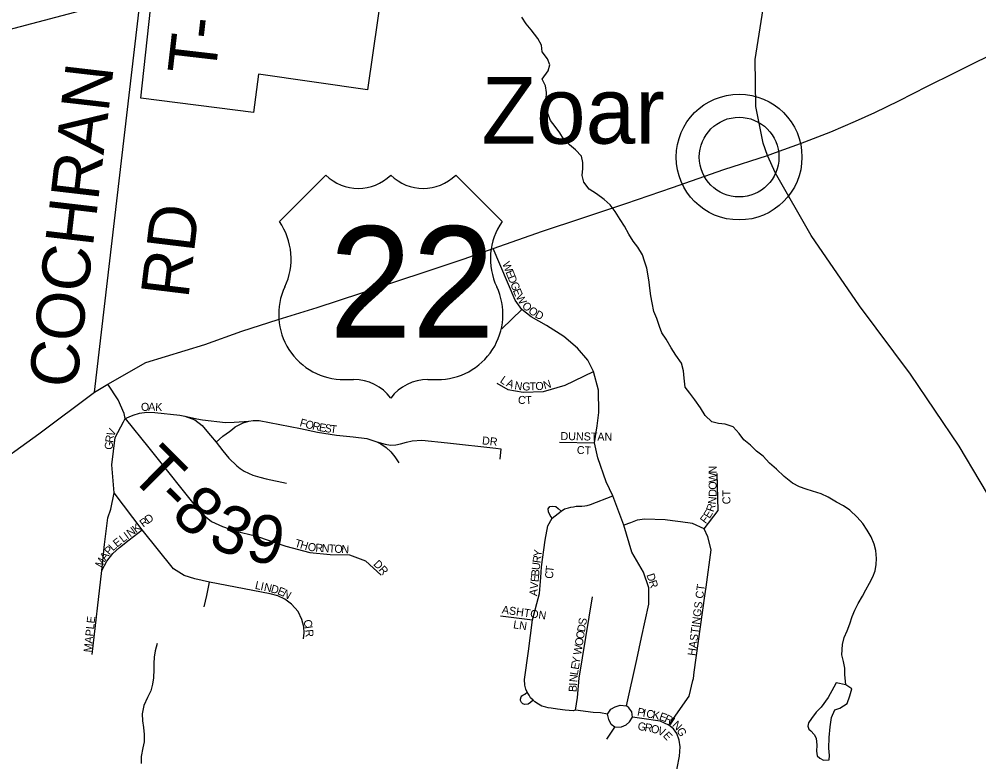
# Model space of a CAD drawing. Extents: x 0 to 34, y -4 to 22.
# Drawn here: x 5.794 to 6.594, y 16.264 to 16.882 of the extents above; entities that cross this region are included whole.
import ezdxf

# ---------------------------------------------------------------- set-up
doc = ezdxf.new("R2010")
doc.units = 0
for name, color, linetype in [('GM_X_Corporation', 7, 'Continuous'), ('GM_X_County_Road', 7, 'Continuous'), ('GM_X_Minor_Lake', 7, 'Continuous'), ('GM_X_Minor_River', 7, 'Continuous'), ('GM_X_Township_Road', 7, 'Continuous'), ('GM_X_Township_Road_Text', 7, 'Continuous'), ('GM_X_Township_Subdivision', 7, 'Continuous'), ('GM_X_Township_Subdivision_Text', 7, 'Continuous'), ('GM_X_Unincorporated', 7, 'Continuous'), ('GM_X_Unincorporated_Text', 7, 'Continuous'), ('GM_X_US_Route', 7, 'Continuous'), ('GM_X_US_Shield', 7, 'Continuous')]:
    doc.layers.add(name, color=color, linetype=linetype)

msp = doc.modelspace()

# ---------------------------------------------------------------- linework, layer by layer
at = {"layer": 'GM_X_Corporation'}
msp.add_lwpolyline([(6.11264, 17.35661), (6.13056, 17.34146), (6.1502, 17.32861), (6.15372, 17.31617), (6.14829, 17.26619), (6.13072, 17.14425), (6.11033, 17.00278), (6.08447, 16.8233), (5.99367, 16.83639), (5.98966, 16.80464), (5.89561, 16.81652), (5.90507, 16.90361), (5.90894, 16.90463), (5.90928, 16.91075), (5.90918, 16.91835), (5.91273, 16.93477), (5.92073, 16.94425), (5.92992, 16.96003), (5.93228, 16.96767), (5.89327, 16.9805), (5.87524, 16.89709), (5.63389, 16.83333)], dxfattribs=at)
at = {"layer": 'GM_X_County_Road'}
msp.add_lwpolyline([(6.61254, 16.4676), (6.57752, 16.52648), (6.53717, 16.58653), (6.49462, 16.64341), (6.45426, 16.70212), (6.42446, 16.75396), (6.41787, 16.7687), (6.41423, 16.779), (6.40811, 16.80957), (6.4076, 16.84871), (6.41599, 16.90164), (6.41166, 16.91348), (6.37222, 16.96469), (6.33546, 17.00676), (6.31619, 17.02672), (6.30338, 17.04608), (6.29642, 17.06037), (6.28477, 17.08116), (6.25889, 17.11808), (6.2527, 17.12703), (6.24616, 17.12926), (6.23635, 17.13047), (6.17768, 17.13907), (6.12342, 17.14557)], dxfattribs=at)
at = {"layer": 'GM_X_Minor_Lake'}
for points in [[(6.47509, 16.32945), (6.47312, 16.32575), (6.46835, 16.31732), (6.46279, 16.30917), (6.4584, 16.305), (6.45452, 16.29976), (6.45201, 16.29608)], [(6.48307, 16.32764), (6.47509, 16.32945)], [(6.45201, 16.29608), (6.45141, 16.29342), (6.45241, 16.29072), (6.45398, 16.28934), (6.45685, 16.28633), (6.45838, 16.28336), (6.45903, 16.27746), (6.45863, 16.27239), (6.45934, 16.26863), (6.46143, 16.26671), (6.4646, 16.26502), (6.46942, 16.26517), (6.46952, 16.26891), (6.46914, 16.27507), (6.46937, 16.28388), (6.47013, 16.29268), (6.47114, 16.30068), (6.47398, 16.30702), (6.47829, 16.30825), (6.48428, 16.31211), (6.48659, 16.31874), (6.48807, 16.32431), (6.48307, 16.32764)]]:
    msp.add_lwpolyline(points, dxfattribs=at)
at = {"layer": 'GM_X_Minor_River'}
for points in [[(6.22968, 16.86058), (6.22657, 16.86624), (6.22107, 16.87328), (6.21687, 16.87843), (6.21322, 16.88383)], [(6.48307, 16.32764), (6.4825, 16.33636), (6.48232, 16.34171), (6.48135, 16.34734), (6.47983, 16.35271), (6.48051, 16.36126), (6.48194, 16.36711), (6.48445, 16.37269), (6.48641, 16.37854), (6.48839, 16.38466), (6.49062, 16.38997), (6.49339, 16.39554), (6.49697, 16.40163), (6.5, 16.40693), (6.50303, 16.41249), (6.5058, 16.4178), (6.50776, 16.42285), (6.50838, 16.42791), (6.50873, 16.43299), (6.50831, 16.43968), (6.50679, 16.44505), (6.50422, 16.45097), (6.5011, 16.45663), (6.49745, 16.46204), (6.49272, 16.46746), (6.48667, 16.47317), (6.48138, 16.477), (6.47555, 16.48003), (6.46839, 16.48415), (6.46255, 16.48692), (6.45537, 16.48917), (6.45005, 16.49086), (6.44446, 16.49282), (6.43863, 16.49585), (6.43177, 16.50131), (6.42545, 16.50729), (6.41965, 16.51246), (6.41439, 16.51815), (6.40885, 16.52252), (6.40385, 16.52741), (6.3983, 16.53178), (6.39438, 16.53718), (6.38939, 16.54261), (6.38274, 16.54485), (6.37713, 16.54548), (6.37154, 16.5469), (6.36601, 16.55207), (6.36211, 16.55855), (6.35741, 16.5653), (6.35322, 16.57072), (6.34929, 16.57586), (6.34835, 16.58336), (6.34791, 16.58925), (6.34615, 16.59569), (6.34144, 16.60245), (6.33753, 16.60839), (6.33337, 16.61567), (6.32999, 16.62108), (6.32793, 16.62619), (6.32564, 16.63291), (6.32333, 16.63882), (6.32185, 16.64606), (6.3206, 16.6517), (6.31991, 16.65812), (6.31919, 16.66322), (6.31848, 16.66857), (6.31751, 16.67474), (6.31547, 16.68065), (6.31369, 16.68602), (6.30978, 16.69224), (6.30612, 16.69737), (6.30248, 16.70331), (6.29884, 16.70978), (6.29519, 16.71546), (6.29102, 16.72194), (6.28684, 16.72762), (6.28183, 16.73197), (6.27549, 16.73689), (6.2694, 16.74072), (6.26495, 16.74641), (6.26344, 16.75205), (6.26407, 16.75792), (6.26416, 16.763), (6.26291, 16.7681), (6.25791, 16.77352), (6.2529, 16.77761), (6.2479, 16.7825), (6.24477, 16.78763), (6.24112, 16.79277), (6.23719, 16.79791), (6.23488, 16.80382), (6.23364, 16.80973), (6.23347, 16.81561), (6.23384, 16.82122), (6.23286, 16.82685), (6.23028, 16.83224), (6.23521, 16.83911), (6.23663, 16.84416), (6.23457, 16.84928), (6.23012, 16.85496), (6.22968, 16.86058)], [(5.90942, 16.36229), (5.90771, 16.35617), (5.90682, 16.35084), (5.90646, 16.3455), (5.90665, 16.34042), (5.90627, 16.33374), (5.90537, 16.3284), (5.90394, 16.32281), (5.90117, 16.31724), (5.89812, 16.31061), (5.89693, 16.30368), (5.8971, 16.29779), (5.89808, 16.29216), (5.89852, 16.28628), (5.89842, 16.2804), (5.89753, 16.27533), (5.89607, 16.26814), (5.89597, 16.26226)]]:
    msp.add_lwpolyline(points, dxfattribs=at)
at = {"layer": 'GM_X_Township_Road'}
for points in [[(5.8572, 16.57167), (5.89878, 16.92871), (5.90307, 16.93929), (5.913, 16.95079), (5.91989, 16.97341)], [(5.93252, 16.55157), (5.94071, 16.54855), (5.94696, 16.54391), (5.95199, 16.53753), (5.95372, 16.53542), (5.95839, 16.52992), (5.96409, 16.52269), (5.96896, 16.51672), (5.97572, 16.51012), (5.97839, 16.50792), (5.98185, 16.50572), (5.98908, 16.5025), (5.99494, 16.50065), (6.0002, 16.49939), (6.01718, 16.49586)], [(5.95839, 16.52992), (5.9641, 16.53485), (5.96956, 16.53876), (5.97198, 16.54075), (5.97446, 16.54259), (5.97667, 16.54373), (5.98108, 16.54601), (5.98567, 16.54752)], [(6.09244, 16.53014), (6.0957, 16.52853), (6.10018, 16.52558), (6.10419, 16.52177), (6.10733, 16.5178), (6.1102, 16.51344), (6.11075, 16.51258)], [(5.94863, 16.39268), (5.95073, 16.40229), (5.95291, 16.41342)]]:
    msp.add_lwpolyline(points, dxfattribs=at)
at = {"layer": 'GM_X_Township_Subdivision'}
for points in [[(6.28405, 16.28258), (6.29061, 16.29252), (6.29634, 16.29266), (6.3002, 16.29439), (6.30287, 16.29692), (6.30553, 16.30079), (6.30487, 16.30519), (6.30242, 16.30869), (6.30034, 16.31025), (6.30899, 16.34895), (6.31283, 16.36709), (6.31902, 16.39484), (6.31902, 16.4085), (6.31454, 16.42152), (6.30487, 16.43825), (6.29818, 16.46067), (6.28895, 16.48528), (6.28349, 16.49688), (6.27658, 16.51673), (6.27371, 16.5293), (6.27612, 16.54363), (6.27735, 16.55473), (6.27711, 16.57324), (6.27291, 16.58891), (6.26823, 16.59816), (6.25959, 16.60828), (6.24824, 16.61789), (6.23369, 16.62702), (6.22086, 16.63418), (6.21322, 16.64035), (6.20754, 16.64824), (6.18941, 16.69127)], [(6.19649, 16.62419), (6.21322, 16.64035)], [(6.19249, 16.57904), (6.20162, 16.57373), (6.21445, 16.57151), (6.23122, 16.57201), (6.24923, 16.57743), (6.27291, 16.58891)], [(5.88123, 16.54693), (5.88264, 16.54958), (5.88187, 16.55367), (5.87692, 16.5651), (5.86827, 16.57813)], [(5.88264, 16.54958), (5.88929, 16.55254), (5.89463, 16.55402), (5.90074, 16.55486), (5.90741, 16.55465), (5.9282, 16.55254), (5.93252, 16.55157), (5.9388, 16.55023), (5.94247, 16.54947), (5.94724, 16.54847), (5.96629, 16.54631), (5.97351, 16.54664), (5.98187, 16.5472), (5.98567, 16.54752), (5.98932, 16.54791), (5.99424, 16.54798), (6.02887, 16.54136), (6.04285, 16.53821), (6.05878, 16.53583), (6.07262, 16.53426), (6.08419, 16.53303), (6.09244, 16.53014), (6.09924, 16.52814), (6.10364, 16.52748), (6.10821, 16.52777), (6.11224, 16.52847), (6.11697, 16.52987), (6.12188, 16.5311), (6.12977, 16.53163), (6.15115, 16.52935), (6.19164, 16.52496), (6.19585, 16.52444), (6.19494, 16.51587)], [(5.85522, 16.35297), (5.86321, 16.42305), (5.8655, 16.44475), (5.86816, 16.46684), (5.87083, 16.47408), (5.8735, 16.48779), (5.87159, 16.51102), (5.87426, 16.53387), (5.88123, 16.54693)], [(5.88264, 16.54958), (5.90244, 16.52511), (5.94547, 16.47141), (5.95461, 16.4638), (5.96375, 16.45961), (5.9748, 16.4558), (5.99117, 16.45199), (6.01669, 16.44323), (6.03649, 16.4379), (6.05362, 16.43638), (6.06962, 16.436), (6.08295, 16.43104), (6.0959, 16.41924)], [(6.24454, 16.52982), (6.27371, 16.5293)], [(6.36512, 16.45781), (6.37686, 16.47297), (6.37601, 16.5037)], [(6.0314, 16.36621), (6.03183, 16.3711), (6.03152, 16.37604), (6.02978, 16.38215), (6.02681, 16.38896), (6.02139, 16.3949), (6.0158, 16.3991), (6.00986, 16.40189), (6.00358, 16.40364), (5.95291, 16.41342), (5.94067, 16.41601), (5.93173, 16.41885), (5.92291, 16.42447), (5.89673, 16.45675), (5.8735, 16.48779)], [(6.28461, 16.30332), (6.27867, 16.30454), (6.27267, 16.30471), (6.25805, 16.30665), (6.25586, 16.30621), (6.24923, 16.30675), (6.24301, 16.30757), (6.23773, 16.30824), (6.23516, 16.30851), (6.23313, 16.30919), (6.22975, 16.31014), (6.227, 16.31156), (6.22407, 16.31352), (6.22258, 16.31487), (6.22055, 16.3169), (6.2192, 16.31907), (6.21773, 16.32154), (6.21662, 16.32407), (6.21567, 16.32746), (6.21554, 16.33233), (6.21865, 16.35587), (6.2222, 16.38184), (6.22783, 16.40382), (6.22896, 16.41728), (6.2297, 16.42608), (6.23263, 16.44821), (6.23476, 16.4602), (6.23836, 16.4666), (6.24595, 16.47233), (6.24889, 16.47425), (6.25201, 16.47514), (6.2541, 16.47574), (6.25619, 16.47618), (6.25858, 16.47649), (6.26066, 16.47649), (6.26319, 16.47649), (6.26573, 16.47678), (6.26767, 16.47708), (6.27035, 16.47797), (6.28895, 16.48528)], [(6.23836, 16.4666), (6.23689, 16.46886), (6.23543, 16.4718), (6.23516, 16.47433), (6.23649, 16.47619), (6.23876, 16.47659), (6.24142, 16.47646), (6.24356, 16.47473), (6.24595, 16.47233)], [(6.33863, 16.46448), (6.3326, 16.46535), (6.3156, 16.46571), (6.3092, 16.46485), (6.30386, 16.46272), (6.29818, 16.46067)], [(6.34545, 16.4635), (6.33863, 16.46448)], [(6.36678, 16.40913), (6.37109, 16.44018), (6.36833, 16.45119), (6.36512, 16.45781), (6.35531, 16.46208), (6.34545, 16.4635)], [(5.86321, 16.42305), (5.8674, 16.43066), (5.87235, 16.43714), (5.87806, 16.44228), (5.88587, 16.44856), (5.89673, 16.45675)], [(6.36579, 16.40204), (6.36678, 16.40913)], [(6.25805, 16.30665), (6.25967, 16.31729), (6.26088, 16.33344), (6.27208, 16.40115)], [(6.35695, 16.3383), (6.36579, 16.40204)], [(6.19538, 16.38523), (6.2222, 16.38184)], [(6.35579, 16.33125), (6.3562, 16.33296), (6.35695, 16.3383)], [(6.33559, 16.29414), (6.3527, 16.31843), (6.35579, 16.33125)], [(6.22258, 16.31487), (6.22052, 16.31307), (6.21852, 16.31171), (6.21582, 16.31142), (6.21406, 16.31207), (6.21294, 16.31318), (6.21224, 16.31459), (6.21218, 16.31594), (6.2127, 16.31765), (6.21335, 16.31859), (6.21417, 16.31918), (6.21558, 16.32006), (6.21773, 16.32154)], [(6.29061, 16.29252), (6.28767, 16.29466), (6.28581, 16.29879), (6.28461, 16.30332), (6.28741, 16.30745), (6.29109, 16.30952), (6.29512, 16.31095), (6.30034, 16.31025)], [(6.33593, 16.21602), (6.3407, 16.24849), (6.34472, 16.2684), (6.34512, 16.276), (6.34445, 16.28173), (6.34241, 16.28735), (6.33966, 16.29119), (6.33559, 16.29414), (6.32836, 16.29748), (6.31326, 16.29972), (6.30553, 16.30079)]]:
    msp.add_lwpolyline(points, dxfattribs=at)
at = {"layer": 'GM_X_Unincorporated'}
for radius in [0.05238, 0.0332]:
    msp.add_circle((6.39427, 16.7674), radius, dxfattribs=at)
at = {"layer": 'GM_X_US_Route'}
for points in [[(6.42449, 16.77108), (6.44542, 16.7786), (6.47082, 16.78829), (6.4914, 16.79732), (6.50738, 16.80461), (6.52744, 16.81418), (6.55131, 16.82632), (6.57383, 16.8377), (6.59254, 16.84705), (6.61178, 16.85612)], [(5.76746, 16.50573), (5.81082, 16.53699), (5.8572, 16.57167), (5.86827, 16.57813), (5.89977, 16.59632), (5.94903, 16.61117), (5.97982, 16.6223), (6.01004, 16.63212), (6.04267, 16.64214), (6.0791, 16.65392), (6.10825, 16.66377), (6.13442, 16.67237), (6.16519, 16.68271), (6.18941, 16.69127), (6.23054, 16.70568), (6.2632, 16.7165), (6.2999, 16.7288), (6.33878, 16.74212), (6.38144, 16.75692), (6.41787, 16.7687), (6.42449, 16.77108)]]:
    msp.add_lwpolyline(points, dxfattribs=at)
at = {"layer": 'GM_X_US_Shield'}
for p, q in [((6.04986, 16.75232), (6.01119, 16.71365)), ((6.19682, 16.71365), (6.15815, 16.75232)), ((6.06533, 16.58217), (6.07307, 16.58217)), ((6.13494, 16.58217), (6.14268, 16.58217))]:
    msp.add_line(p, q, dxfattribs=at)
for centre, radius, start, end in [((6.07693, 16.77994), 0.03867, 225.573, 314.427), ((6.13107, 16.77994), 0.03867, 225.573, 314.427), ((5.96684, 16.6826), 0.05414, 334.54712, 35.00093), ((6.24117, 16.6826), 0.05414, 144.99907, 205.45288), ((6.06473, 16.6363), 0.05414, 154.83192, 270.63826), ((6.14328, 16.6363), 0.05414, 269.36174, 25.16808), ((6.07307, 16.54349), 0.03867, 36.8699, 90), ((6.13494, 16.54349), 0.03867, 90, 143.1301)]:
    msp.add_arc(centre, radius, start, end, dxfattribs=at)

# ---------------------------------------------------------------- texts
at = {"layer": 'GM_X_Township_Road_Text'}
for s, rotation, p in [('-', 83.46765, (5.9611, 16.86431)), ('T', 83.41559, (5.95767, 16.83455)), ('COCHRAN', 83.36409, (5.84197, 16.57389)), ('RD', 83.05913, (5.93525, 16.64883)), ('T', 315.02728, (5.88478, 16.50244)), ('-', 315.35688, (5.90613, 16.48112)), ('8', 318.53734, (5.91959, 16.46793)), ('3', 337.90899, (5.95053, 16.44388)), ('9', 349.48191, (5.9818, 16.43215))]:
    msp.add_text(s, height=0.04, rotation=rotation, dxfattribs=at).set_placement(p)
at = {"layer": 'GM_X_Township_Subdivision_Text'}
for s, height, rotation, p in [('W', 0.00667, 291.75459, (6.1967, 16.67871)), ('E', 0.00667, 291.75573, (6.19952, 16.67162)), ('D', 0.00667, 291.76547, (6.20126, 16.66726)), ('G', 0.00667, 291.76083, (6.20344, 16.66182)), ('E', 0.00667, 291.74561, (6.20561, 16.65637)), ('W', 0.00667, 300.06218, (6.20781, 16.65106)), ('O', 0.00667, 315.36575, (6.21282, 16.64292)), ('O', 0.00667, 325.994, (6.21803, 16.63795)), ('D', 0.00667, 331.61208, (6.22351, 16.6343)), ('L', 0.00667, 325.92347, (6.19449, 16.58013)), ('A', 0.00667, 337.1131, (6.19963, 16.57682)), ('N', 0.00667, 351.21614, (6.20675, 16.57406)), ('G', 0.00667, 358.54027, (6.21348, 16.57308)), ('T', 0.00667, 2.2403, (6.21981, 16.57293)), ('O', 0.00667, 4.24718, (6.22476, 16.57313)), ('N', 0.00667, 16.85341, (6.23218, 16.57386)), ('O', 0.00667, 4.41882, (5.89609, 16.55571)), ('A', 0.00667, 358.62307, (5.90176, 16.55616)), ('K', 0.00667, 357.39843, (5.90759, 16.55602)), ('C', 0.00667, 351.17259, (6.20959, 16.56232)), ('T', 0.00667, 3.29197, (6.21634, 16.56143)), ('F', 0.00667, 344.48613, (6.02763, 16.54332)), ('O', 0.00667, 345.96178, (6.03234, 16.54201)), ('R', 0.00667, 347.00072, (6.03816, 16.54056)), ('E', 0.00667, 350.65252, (6.04376, 16.53928)), ('S', 0.00667, 351.71815, (6.04852, 16.5385)), ('V', 0.00667, 65.28287, (5.87308, 16.5339)), ('T', 0.00667, 352.602, (6.05328, 16.53781)), ('DUNSTAN', 0.006667, 359.13245, (6.24541, 16.53168)), ('G', 0.00667, 86.34731, (5.87219, 16.52344)), ('R', 0.00667, 82.64606, (5.87255, 16.52918)), ('DR', 0.006667, 353.99459, (6.17981, 16.52814)), ('CT', 0.006667, 356.82151, (6.25891, 16.52022)), ('N', 0.00667, 90, (6.37555, 16.50383)), ('W', 0.00667, 90, (6.37555, 16.4962)), ('O', 0.00667, 90, (6.37555, 16.49033)), ('D', 0.00667, 90, (6.37555, 16.48447)), ('CT', 0.006667, 90, (6.38702, 16.4782)), ('N', 0.00667, 83.71692, (6.37486, 16.47784)), ('E', 0.00667, 58.58459, (6.36969, 16.46584)), ('R', 0.00667, 71.15076, (6.37281, 16.47129)), ('R', 0.00667, 36.69999, (5.89778, 16.4586)), ('D', 0.00667, 36.68628, (5.90201, 16.46175)), ('F', 0.00667, 52.30151, (6.36636, 16.46147)), ('N', 0.00667, 36.72282, (5.88696, 16.45053)), ('K', 0.00667, 36.70381, (5.89166, 16.45404)), ('E', 0.00667, 39.07795, (5.87587, 16.44197)), ('L', 0.00667, 36.91906, (5.88086, 16.44596)), ('I', 0.00667, 36.68628, (5.8846, 16.44877)), ('T', 0.00667, 343.25888, (6.02342, 16.44303)), ('P', 0.00667, 49.29204, (5.86957, 16.43546)), ('L', 0.00667, 42.50709, (5.87249, 16.43887)), ('H', 0.00667, 343.27485, (6.02791, 16.44168)), ('O', 0.00667, 350.56964, (6.03443, 16.43978)), ('R', 0.00667, 357.02236, (6.04104, 16.43873)), ('N', 0.00667, 356.96079, (6.04631, 16.43846)), ('T', 0.00667, 356.96567, (6.05217, 16.43814)), ('O', 0.00667, 356.96079, (6.05685, 16.4379)), ('N', 0.00667, 356.98658, (6.06271, 16.43759)), ('M', 0.00667, 60.66407, (5.86297, 16.4248)), ('A', 0.00667, 55.11543, (5.86633, 16.43079)), ('R', 0.00667, 82.23045, (6.22868, 16.42884)), ('Y', 0.00667, 82.15116, (6.2294, 16.43407)), ('DR', 0.006667, 312.88011, (6.08908, 16.42802)), ('U', 0.00667, 83.44978, (6.22802, 16.42305)), ('T', 0.00667, 83.20714, (6.23949, 16.42114)), ('E', 0.00667, 84.52858, (6.22707, 16.41315)), ('B', 0.00667, 84.51784, (6.22752, 16.41782)), ('C', 0.00667, 86.28124, (6.23916, 16.41596)), ('D', 0.00667, 288.13773, (6.31698, 16.41936)), ('L', 0.00667, 347.60753, (5.99045, 16.40786)), ('I', 0.00667, 347.57551, (5.99504, 16.40685)), ('N', 0.00667, 347.60828, (5.99791, 16.40622)), ('D', 0.00667, 344.64904, (6.00355, 16.40498)), ('E', 0.00667, 337.87394, (6.00901, 16.40349)), ('V', 0.00667, 84.54134, (6.22651, 16.40731)), ('R', 0.00667, 287.56702, (6.3188, 16.4138)), ('HASTINGS CT', 0.0066667, 82.40471, (6.35796, 16.35165)), ('N', 0.00667, 330.72677, (6.01316, 16.40182)), ('A', 0.00667, 84.52858, (6.22595, 16.40147)), ('ASHTON', 0.006667, 351.87045, (6.19629, 16.38734)), ('MAPLE', 0.006667, 83.92636, (5.8546, 16.35455)), ('C', 0.00667, 278.97516, (6.03132, 16.38163)), ('LN', 0.006667, 351.02147, (6.20568, 16.37496)), ('D', 0.00667, 80.54732, (6.26571, 16.37136)), ('S', 0.00667, 80.53318, (6.26668, 16.37715)), ('I', 0.00667, 278.95219, (6.03214, 16.37641)), ('R', 0.00667, 275.32636, (6.03259, 16.37363)), ('O', 0.00667, 80.53767, (6.26475, 16.36557)), ('W', 0.00667, 80.52385, (6.26253, 16.35226)), ('O', 0.00667, 80.54732, (6.26379, 16.35979)), ('E', 0.00667, 80.53318, (6.2605, 16.3401)), ('Y', 0.00667, 80.54732, (6.26128, 16.34474)), ('L', 0.00667, 80.86548, (6.25976, 16.33548)), ('N', 0.00667, 84.61561, (6.25923, 16.32975)), ('B', 0.00667, 87.03571, (6.25881, 16.32163)), ('I', 0.00667, 87.02626, (6.25908, 16.3269)), ('P', 0.00667, 349.14542, (6.30896, 16.30227)), ('I', 0.00667, 349.13594, (6.31357, 16.30139)), ('C', 0.00667, 349.14897, (6.31645, 16.30083)), ('K', 0.00667, 349.14621, (6.32164, 16.29984)), ('E', 0.00667, 340.58876, (6.32714, 16.2988)), ('R', 0.00667, 334.8467, (6.33141, 16.29731)), ('I', 0.00667, 327.08612, (6.33598, 16.29518)), ('N', 0.00667, 314.95364, (6.33815, 16.29382)), ('G', 0.00667, 350.20348, (6.30936, 16.29038)), ('R', 0.00667, 349.49968, (6.31512, 16.28939)), ('O', 0.00667, 345.61915, (6.3202, 16.28845)), ('V', 0.00667, 336.24171, (6.32561, 16.28709)), ('E', 0.00667, 312.64301, (6.33039, 16.28514)), ('G', 0.00667, 296.89737, (6.34197, 16.29012))]:
    msp.add_text(s, height=height, rotation=rotation, dxfattribs=at).set_placement(p)
at = {"layer": 'GM_X_Unincorporated_Text'}
msp.add_text('Zoar', height=0.055556, rotation=0.00001, dxfattribs=at).set_placement((6.17968, 16.77855))
at = {"layer": 'GM_X_US_Shield'}
msp.add_text('22', height=0.092813, dxfattribs=at).set_placement((6.05263, 16.61697))

doc.saveas('drawing.dxf')
